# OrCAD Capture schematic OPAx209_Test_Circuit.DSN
size A; title: OPAx209 2.2-nV/vHz, Low-Power, 36-V Operational Amplifier; rev: 1.5; note: Datasheet: SBOS426D   EVM: N/A
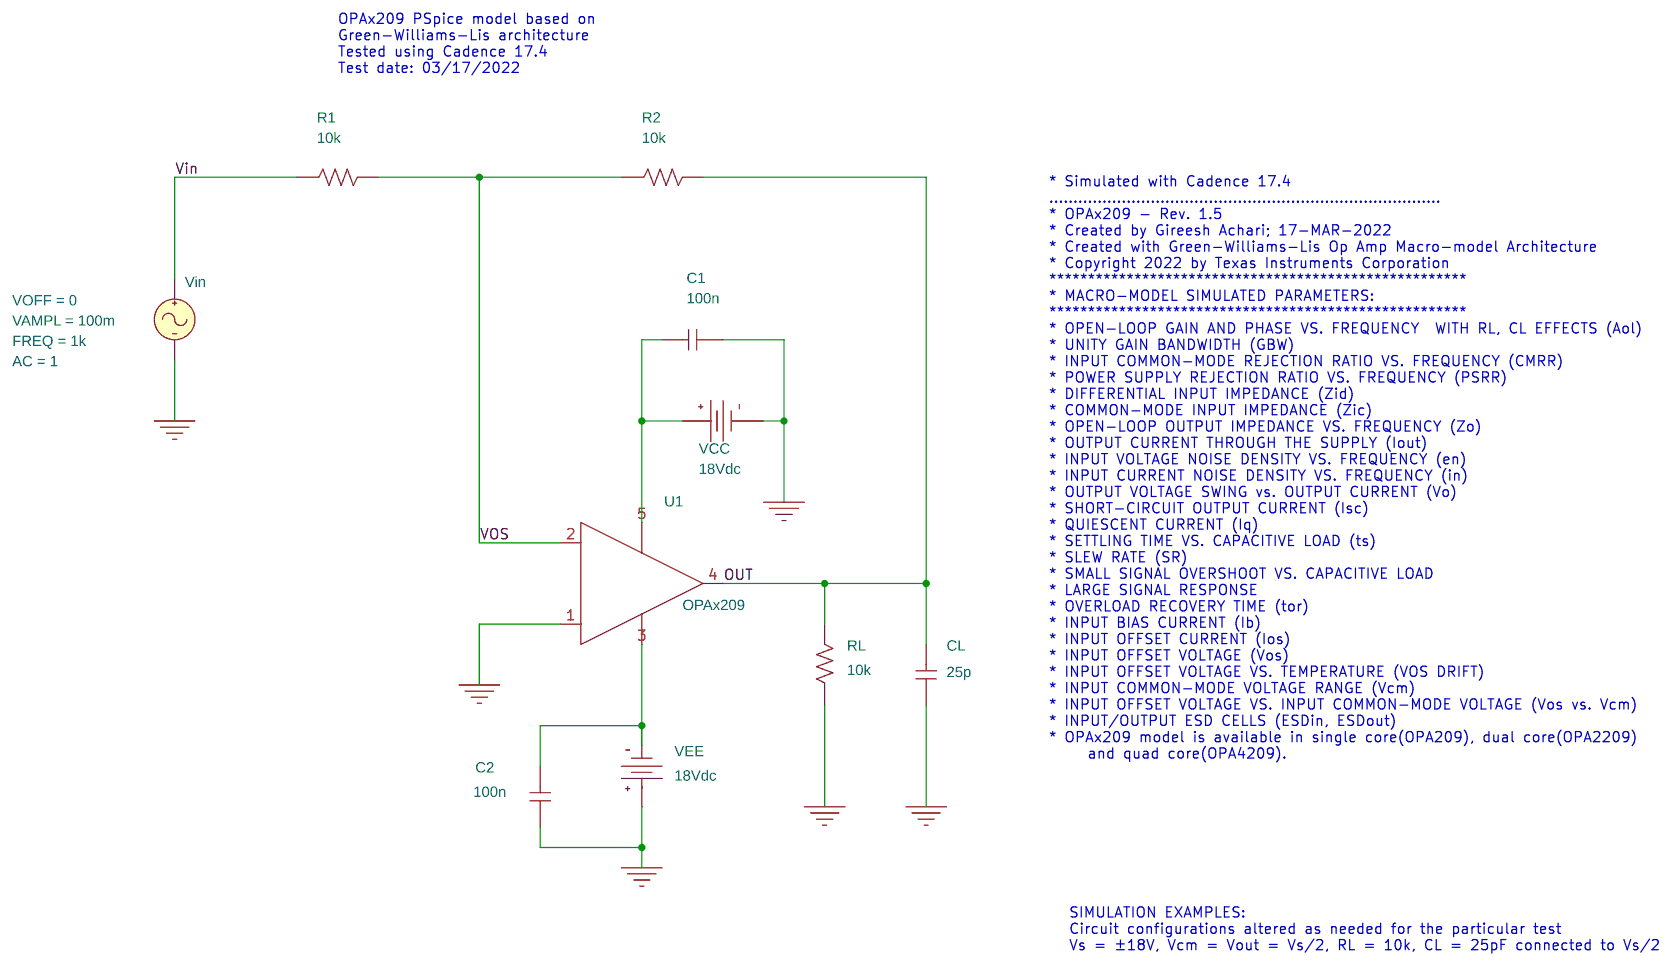
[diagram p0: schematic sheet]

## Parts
C1  100n  [cap196]
C2  100n  [cap196]
CL  25p  [cap196]
R1  10k  [AXRC05]
R2  10k  [AXRC05]
RL  10k  [AXRC05]
U1  OPAx209
VCC  VDC
VEE  VDC
Vin  VSIN

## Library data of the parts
C1 C2 CL = C
R1 R2 RL = R
U1 = OPAx209
VCC VEE = VDC: DC: 18Vdc
Vin = VSIN: AC: 1; FREQ: 1k; VAMPL: 100m; VOFF: 0

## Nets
Vin: R1.1 Vin.1(+)
0: C1.2 C2.1 CL.2 RL.1 U1.1(+) VCC.1(-) VEE.0(+) Vin.2(-)
OUT: CL.1 R2.2 RL.2 U1.4(OUT)
VOS: R1.2 R2.1 U1.2(-)
N27303: C1.1 U1.5(V+) VCC.0(+)
N27354: C2.2 U1.3(V-) VEE.1(-)

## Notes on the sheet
- OPAx209 PSpice model based on
  Green-Williams-Lis architecture
  Tested using Cadence 17.4
  Test date: 03/17/2022
- * Simulated with Cadence 17.4
  .................................................................................
  * OPAx209 - Rev. 1.5
  * Created by Gireesh Achari; 17-MAR-2022
  * Created with Green-Williams-Lis Op Amp Macro-model Architecture
  * Copyright 2022 by Texas Instruments Corporation
  ******************************************************
  * MACRO-MODEL SIMULATED PARAMETERS:
  ******************************************************
  * OPEN-LOOP GAIN AND PHASE VS. FREQUENCY  WITH RL, CL EFFECTS (Aol)
  * UNITY GAIN BANDWIDTH (GBW)
  * INPUT COMMON-MODE REJECTION RATIO VS. FREQUENCY (CMRR)
  * POWER SUPPLY REJECTION RATIO VS. FREQUENCY (PSRR)
  * DIFFERENTIAL INPUT IMPEDANCE (Zid)
  * COMMON-MODE INPUT IMPEDANCE (Zic)
  * OPEN-LOOP OUTPUT IMPEDANCE VS. FREQUENCY (Zo)
  * OUTPUT CURRENT THROUGH THE SUPPLY (Iout)
  * INPUT VOLTAGE NOISE DENSITY VS. FREQUENCY (en)
  * INPUT CURRENT NOISE DENSITY VS. FREQUENCY (in)
  * OUTPUT VOLTAGE SWING vs. OUTPUT CURRENT (Vo)
  * SHORT-CIRCUIT OUTPUT CURRENT (Isc)
  * QUIESCENT CURRENT (Iq)
  * SETTLING TIME VS. CAPACITIVE LOAD (ts)
  * SLEW RATE (SR)
  * SMALL SIGNAL OVERSHOOT VS. CAPACITIVE LOAD
  * LARGE SIGNAL RESPONSE
  * OVERLOAD RECOVERY TIME (tor)
  * INPUT BIAS CURRENT (Ib)
  * INPUT OFFSET CURRENT (Ios)
  * INPUT OFFSET VOLTAGE (Vos)
  * INPUT OFFSET VOLTAGE VS. TEMPERATURE (VOS DRIFT)
  * INPUT COMMON-MODE VOLTAGE RANGE (Vcm)
  * INPUT OFFSET VOLTAGE VS. INPUT COMMON-MODE VOLTAGE (Vos vs. Vcm)
  * INPUT/OUTPUT ESD CELLS (ESDin, ESDout)
  * OPAx209 model is available in single core(OPA209), dual core(OPA2209)
       and quad core(OPA4209).
- SIMULATION EXAMPLES:
  Circuit configurations altered as needed for the particular test
  Vs = ±18V, Vcm = Vout = Vs/2, RL = 10k, CL = 25pF connected to Vs/2
